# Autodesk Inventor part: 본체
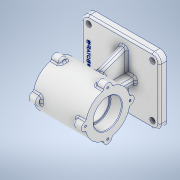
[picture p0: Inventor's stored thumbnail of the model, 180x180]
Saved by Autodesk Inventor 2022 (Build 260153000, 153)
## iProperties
Created: 2023-05
Part Number: 본체
Material: 알루미늄 6061
Document SubType Name: Modeling
Designer: Admin
Mass: 1214.97 g
Surface Area: 797.904 cm^2
Volume: 449.989 cm^3
Density: 2.7 g/cm^3
Appearance: 알루미늄 - 평지
Author: Admin
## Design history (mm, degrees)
sketch "스케치1"
  geometry: L1 (-91, 0)-(91, 0) reference; L2 (0, -77)-(0, 77) reference; L3 (-65, 55)-(65, 55); L4 (65, 55)-(65, -55); L5 (65, -55)-(-65, -55); L6 (-65, -55)-(-65, 55); 1 further point
  constraints: 8 end point, 2 parallel, 2 symmetric about line, 1 horizontal, 1 perpendicular
  dimensions: "d0" = 130 distance of L3.start L3.end; "d1" = 110 distance of L3.end L4.end
extrude "돌출1" new body sketch "스케치1" distance "d2" = 12; taper "d3" = 0 deg
sketch "스케치2"
  geometry: L1 (91, 0)-(-91, 0) reference; L2 (0, -2.4)-(0, 14.4) reference; L3 (74.462, 82)-(-95.904, 82); L4 (-65, 12)-(65, 12) reference; L5 (15, 12)-(-25, 12); L6 (-25, 12)-(-25, 82); L7 (-25, 82)-(15, 82); L8 (15, 82)-(15, 12); L9 (-5, 82)-(-5, 12); L10 (65, 12)-(-65, 12) reference; L11 (65, 0)-(65, 12) reference; 1 further point
  constraints: 12 end point, 3 point on line, 2 horizontal, 2 parallel, 2 perpendicular, 1 midpoint
  dimensions: "d4" = 82 distance between parallel lines of L1 L3; "d5" = 40 distance of L5.end L5.start; "d39" = 70 distance from line of L11 L9.start
extrude "돌출2" join sketch "스케치2" stored distance "d6" = 10; taper "d7" = 0 deg
sketch "스케치3"
  geometry: L1 (-68.005, 82)-(84.117, 82); L2 (55, 0)-(-55, 0) reference; L3 (55, 12)-(-55, 12) reference; L4 (41, 12)-(15.522, 82); L5 (0, -16.4)-(0, 98.4) reference; L6 (-41, 12)-(-15.522, 82); L7 (-15.522, 82)-(15.522, 82); L8 (-41, 12)-(41, 12); 1 further point
  constraints: 10 end point, 2 collinear, 2 point on line, 2 symmetric about line, 1 horizontal
  dimensions: "d8" = 82 distance between parallel lines of L2 L1; "d9" = 110 deg angle of L3 L4; "d10" = 14 distance of L3.start L4.start
extrude "돌출3" join sketch "스케치3" distance "d11" = 10; taper "d12" = 0 deg
sketch "스케치4"
  geometry: L1 (-79.667, 82)-(94.507, 82); L2 (65, 0)-(-65, 0) reference; L3 (-48.5, 82)-(38.5, 82); L4 (38.5, 82)-(38.5, 119); L5 (38.5, 119)-(-48.5, 119); L6 (-48.5, 119)-(-48.5, 82); L7 (129.342, 0)-(-114.502, 0) reference; L8 (0, -30.969)-(0, 185.812) reference; L9 (-25, 82)-(-10, 82) reference; L10 (-5, 119)-(-5, 82); L11 (-10, 82)-(-25, 82) reference; L12 (0, 82)-(-10, 82) reference; L13 (-5, 82)-(-5, 0); 1 further point
  constraints: 14 end point, 3 perpendicular, 3 point on line, 2 horizontal, 2 midpoint, 2 parallel
  dimensions: "d13" = 82 distance between parallel lines of L2 L1; "d14" = 87 distance of L4.end L5.end; "d15" = 74 diameter of L5.end L1
revolve "회전1" sketch "스케치4" stored, may be unused: angle "d16" = 90 deg
sketch "스케치5"
  geometry: L1 (107.2, 0)-(-69.2, 0) reference; L2 (0, -60.028)-(0, 85.001); L3 (82, -55)-(82, 55) reference; C1 r 37 at (0, 0); C2 r 7 at (-37, 0); C3 r 7 at (0, -37); C4 r 7 at (37, 0); C5 r 7 at (0, 37); 5 further points
  constraints: 5 centre point, 3 point on line, 2 coincident, 2 end point, 1 horizontal alignment, 1 vertical, 12 other
  dimensions: "d17" = 82 distance between parallel lines of L3 L2; "d19" = 37 radius of C1; "d22" = 7 radius of C2; "d26" = 360 deg dimension on C1.centre C2.centre (derived)
extrude "돌출4" join sketch "스케치5" distance "d28" = 14; taper "d29" = 0 deg
sketch "스케치6"
  geometry: L1 (-48.5, 89)-(-48.5, 75) reference; L2 (-48.5, 82)-(92.583, 82); L3 (-48.5, 82)-(-29.5, 82); L4 (-29.5, 82)-(-29.5, 105.5); L5 (-29.5, 105.5)-(-48.5, 105.5); L6 (-48.5, 105.5)-(-48.5, 82); L7 (-29.5, 82)-(19.5, 82); L8 (19.5, 82)-(19.5, 103); L9 (19.5, 103)-(-29.5, 103); L10 (-29.5, 103)-(-29.5, 82); L11 (38.5, 119)-(38.5, 119) reference; L12 (19.5, 82)-(38.5, 82); L13 (38.5, 82)-(38.5, 105.5); L14 (38.5, 105.5)-(19.5, 105.5); L15 (19.5, 105.5)-(19.5, 82); 5 further points
  constraints: 26 end point, 6 parallel, 4 horizontal, 3 perpendicular, 2 point on line, 1 midpoint
  dimensions: "d30" = 19 distance of L4.end L5.end; "d31" = 19 distance of L13.end L14.end; "d32" = 47 diameter of L5.end L2; "d33" = 42 diameter of L9 L2
revolve "회전2" sketch "스케치6" stored, may be unused: angle "d34" = 90 deg
fillet "모깎기1" dims "d35" = 12
sketch "스케치7"
  geometry: L1 (-91.497, 0)-(93.982, 0) reference; L2 (0, -79.982)-(0, 77.497) reference; C1 r 4.5 at (53, -43); C2 r 4.5 at (53, 43); C3 r 4.5 at (-53, 43); C4 r 4.5 at (-53, -43); A1 r 12 centre (53, -43) between (53, -55) and (65, -43) reference; 1 further point
  constraints: 4 centre point, 3 symmetric about line, 1 coincident, 3 other
  dimensions: "d38" = 9 diameter of C1
node "작업 평면1"
extrude "돌출5" cut sketch "스케치7" extent not by distance; stored distance "d41" = 10; taper "d42" = 0 deg
sketch "스케치9"
  geometry: L1 (5, 77.966)-(5, -112.248); L2 (-91, 0)-(91, 0) reference; 2 further points
  constraints: 2 end point, 1 point on line, 1 vertical, 1 other
  dimensions: "d44" = 5 distance from line of point (0, 0) L1; "d45" = 58 distance from line of L1 point (-53, 0)
feature "엠보싱1" sketch "스케치9" dims "d0" = 130, "d1" = 110, "d46" = 0.5, "d47" = 0
fillet "모깎기2" dims "d48" = 3
fillet "모깎기3" dims "d49" = 3
fillet "모깎기4" dims "d50" = 3
sketch "스케치10"
  geometry: A1 r 7 centre (37, 37) between (43.889, 38.239) and (30.111, 38.239) reference; A2 r 7 centre (0, 0) between (-1.239, 6.889) and (-1.239, -6.889) reference; A3 r 7 centre (37, -37) between (30.111, -38.239) and (43.889, -38.239) reference; A4 r 7 centre (74, 0) between (75.239, -6.889) and (75.239, 6.889) reference; 5 further points
  constraints: 4 coincident
hole "구멍1" sketch "스케치10" at (37, 37), (0, 0), (37, -37), (74, 0) diameter "d51" = 3.45873; stored, may be unused: countersink angle "d55" = 90 deg, drill point angle "d57" = 118 deg; dims "d52" = 8, "d53" = 4, "d54" = 2, "d56" = 10
chamfer "모따기1" distance "d58" = 1; stored, may be unused: second distance "d59" = 2, angle "d60" = 45 deg
fillet "모깎기5" dims "d61" = 1
node "솔리드1"
mirror "미러2"
mirror "미러3"
feature "A9D066F2-1C7D-4E18-AEED-F7BC21143FA4" dims "d51" = 3.45873, "d52" = 8, "d53" = 4, "d54" = 2, "d55" = 90 deg, "d56" = 10, "d57" = 118 deg
other parameters: "d40" = -43.5
